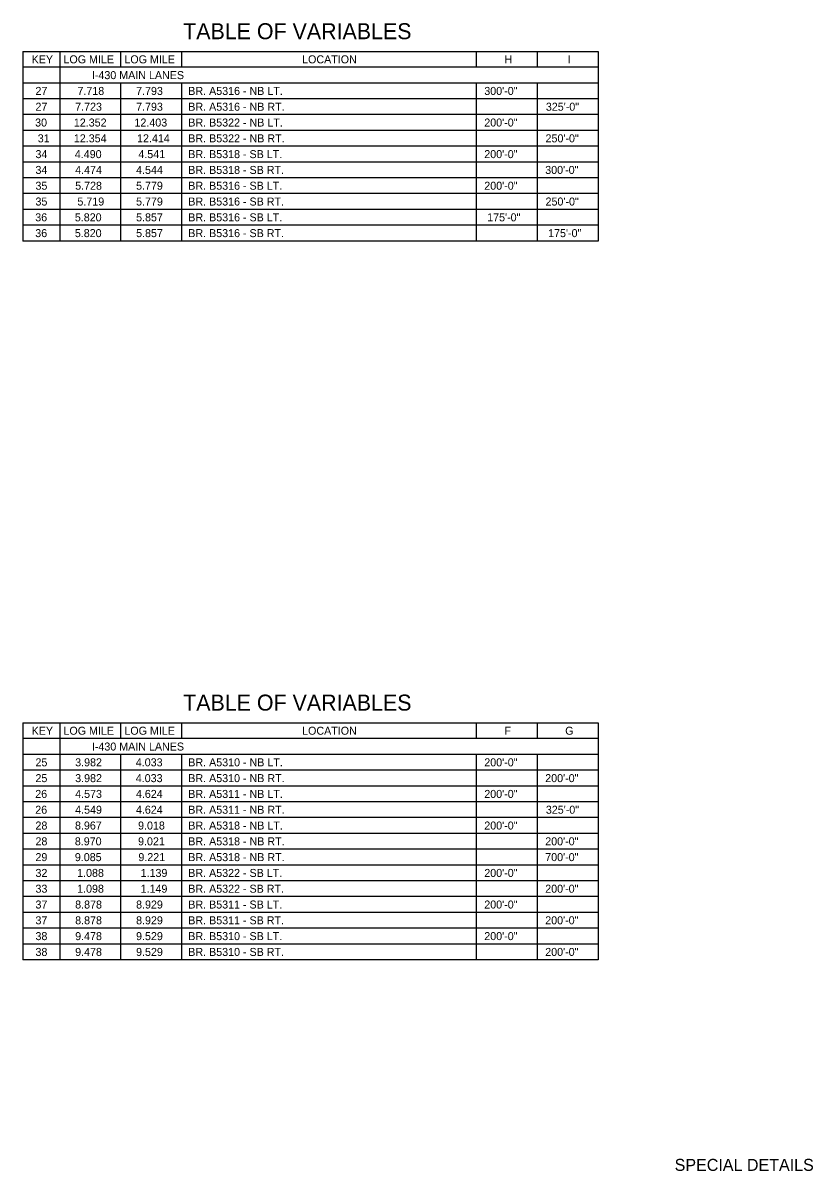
# Model space of a CAD drawing. Extents: x 1373853 to 1374003, y 380191 to 380927.
# Drawn here: x 1373943.9 to 1374003.2, y 380190.6 to 380276.6 of the extents above; entities that cross this region are included whole.
import ezdxf

# ---------------------------------------------------------------- set-up
doc = ezdxf.new("R2010")
doc.units = 0
for name, color, linetype in [('2', 7, 'Continuous'), ('8', 7, 'Continuous'), ('G-ANNO-TEXT', 7, 'Continuous'), ('Plan Notes', 7, 'Continuous')]:
    doc.layers.add(name, color=color, linetype=linetype)

msp = doc.modelspace()

# ---------------------------------------------------------------- linework, layer by layer
at = {"layer": 'Plan Notes'}
for p, q in [((1373943.931, 380274.494), (1373987.072, 380274.494)), ((1373943.931, 380274.494), (1373943.931, 380260.28)), ((1373946.688, 380274.494), (1373946.688, 380260.28)), ((1373951.258, 380274.494), (1373951.258, 380273.31)), ((1373955.827, 380274.494), (1373955.827, 380273.31)), ((1373977.932, 380274.494), (1373977.932, 380273.31)), ((1373982.502, 380274.494), (1373982.502, 380273.31)), ((1373987.072, 380274.494), (1373987.072, 380260.28)), ((1373951.258, 380272.125), (1373951.258, 380260.28)), ((1373955.827, 380272.125), (1373955.827, 380260.28)), ((1373977.932, 380272.125), (1373977.932, 380260.28)), ((1373982.502, 380272.125), (1373982.502, 380260.28)), ((1373943.931, 380224.155), (1373987.072, 380224.155)), ((1373943.931, 380224.155), (1373943.931, 380206.387)), ((1373946.688, 380224.155), (1373946.688, 380206.387)), ((1373951.258, 380224.155), (1373951.258, 380222.971)), ((1373955.827, 380224.155), (1373955.827, 380222.971)), ((1373977.932, 380224.155), (1373977.932, 380222.971)), ((1373982.502, 380224.155), (1373982.502, 380222.971)), ((1373987.072, 380224.155), (1373987.072, 380206.387)), ((1373951.258, 380221.786), (1373951.258, 380206.387)), ((1373955.827, 380221.786), (1373955.827, 380206.387)), ((1373977.932, 380221.786), (1373977.932, 380206.387)), ((1373982.502, 380221.786), (1373982.502, 380206.387))]:
    msp.add_line(p, q, dxfattribs=at)
for points in [[(1373987.072, 380273.31), (1373943.931, 380273.31)], [(1373987.072, 380272.125), (1373943.931, 380272.125)], [(1373987.072, 380270.941), (1373943.931, 380270.941)], [(1373987.072, 380269.756), (1373943.931, 380269.756)], [(1373987.072, 380268.572), (1373943.931, 380268.572)], [(1373987.072, 380267.387), (1373943.931, 380267.387)], [(1373987.072, 380267.387), (1373943.931, 380267.387)], [(1373987.072, 380266.203), (1373943.931, 380266.203)], [(1373987.072, 380265.018), (1373943.931, 380265.018)], [(1373987.072, 380263.834), (1373943.931, 380263.834)], [(1373987.072, 380262.649), (1373943.931, 380262.649)], [(1373987.072, 380262.649), (1373943.931, 380262.649)], [(1373987.072, 380261.465), (1373943.931, 380261.465)], [(1373987.072, 380260.28), (1373943.931, 380260.28)], [(1373987.072, 380222.971), (1373943.931, 380222.971)], [(1373987.072, 380221.786), (1373943.931, 380221.786)], [(1373987.072, 380220.602), (1373943.931, 380220.602)], [(1373987.072, 380219.417), (1373943.931, 380219.417)], [(1373987.072, 380218.233), (1373943.931, 380218.233)], [(1373987.072, 380217.048), (1373943.931, 380217.048)], [(1373987.072, 380217.048), (1373943.931, 380217.048)], [(1373987.072, 380215.864), (1373943.931, 380215.864)], [(1373987.072, 380214.679), (1373943.931, 380214.679)], [(1373987.072, 380213.494), (1373943.931, 380213.494)], [(1373987.072, 380212.31), (1373943.931, 380212.31)], [(1373987.072, 380212.31), (1373943.931, 380212.31)], [(1373987.072, 380211.125), (1373943.931, 380211.125)], [(1373987.072, 380209.941), (1373943.931, 380209.941)], [(1373987.072, 380208.756), (1373943.931, 380208.756)], [(1373987.072, 380207.572), (1373943.931, 380207.572)], [(1373987.072, 380206.387), (1373943.931, 380206.387)]]:
    msp.add_lwpolyline(points, dxfattribs=at)

# ---------------------------------------------------------------- texts
at = {"layer": '2'}
for s, p in [('KEY', (1373944.582, 380273.602)), ('LOG MILE', (1373946.969, 380273.602)), ('LOG MILE', (1373951.539, 380273.602)), ('LOCATION', (1373964.869, 380273.602)), ('H', (1373980.047, 380273.602)), ('I', (1373984.787, 380273.602)), ('I-430 MAIN LANES', (1373949.101, 380272.418)), ('27', (1373944.87, 380271.233)), ('7.718', (1373948.018, 380271.233)), ('7.793', (1373952.418, 380271.233)), ('BR. A5316 - NB LT.', (1373956.331, 380271.233)), ('300\'-0"', (1373978.532, 380271.233)), ('27', (1373944.87, 380270.049)), ('7.723', (1373947.848, 380270.049)), ('7.793', (1373952.418, 380270.049)), ('BR. A5316 - NB RT.', (1373956.331, 380270.049)), ('325\'-0"', (1373983.15, 380270.049)), ('30', (1373944.844, 380268.864)), ('12.352', (1373947.749, 380268.864)), ('12.403', (1373952.295, 380268.864)), ('BR. B5322 - NB LT.', (1373956.331, 380268.864)), ('200\'-0"', (1373978.532, 380268.864)), ('31', (1373945.04, 380267.68)), ('12.354', (1373947.749, 380267.68)), ('12.414', (1373952.489, 380267.68)), ('BR. B5322 - NB RT.', (1373956.331, 380267.68)), ('250\'-0"', (1373983.126, 380267.68)), ('34', (1373944.87, 380266.495)), ('4.490', (1373947.822, 380266.495)), ('4.541', (1373952.588, 380266.495)), ('BR. B5318 - SB LT.', (1373956.331, 380266.495)), ('200\'-0"', (1373978.532, 380266.495)), ('34', (1373944.87, 380265.31)), ('4.474', (1373947.848, 380265.31)), ('4.544', (1373952.418, 380265.31)), ('BR. B5318 - SB RT.', (1373956.331, 380265.31)), ('300\'-0"', (1373983.102, 380265.31)), ('35', (1373944.87, 380264.126)), ('5.728', (1373947.848, 380264.126)), ('5.779', (1373952.416, 380264.126)), ('BR. B5316 - SB LT.', (1373956.331, 380264.126)), ('200\'-0"', (1373978.532, 380264.126)), ('35', (1373944.87, 380262.941)), ('5.719', (1373948.016, 380262.941)), ('5.779', (1373952.416, 380262.941)), ('BR. B5316 - SB RT.', (1373956.331, 380262.941)), ('250\'-0"', (1373983.126, 380262.941)), ('36', (1373944.853, 380261.757)), ('5.820', (1373947.822, 380261.757)), ('5.857', (1373952.418, 380261.757)), ('BR. B5316 - SB LT.', (1373956.331, 380261.757)), ('175\'-0"', (1373978.75, 380261.757)), ('36', (1373944.853, 380260.572)), ('5.820', (1373947.822, 380260.572)), ('5.857', (1373952.418, 380260.572)), ('BR. B5316 - SB RT.', (1373956.331, 380260.572)), ('175\'-0"', (1373983.32, 380260.572)), ('KEY', (1373944.582, 380223.263)), ('LOG MILE', (1373946.969, 380223.263)), ('LOG MILE', (1373951.539, 380223.263)), ('LOCATION', (1373964.869, 380223.263)), ('F', (1373980.044, 380223.263)), ('G', (1373984.6, 380223.263)), ('I-430 MAIN LANES', (1373949.101, 380222.078)), ('25', (1373944.87, 380220.894)), ('3.982', (1373947.848, 380220.894)), ('4.033', (1373952.394, 380220.894)), ('BR. A5310 - NB LT.', (1373956.331, 380220.894)), ('200\'-0"', (1373978.532, 380220.894)), ('25', (1373944.87, 380219.709)), ('3.982', (1373947.848, 380219.709)), ('4.033', (1373952.394, 380219.709)), ('BR. A5310 - NB RT.', (1373956.331, 380219.709)), ('200\'-0"', (1373983.102, 380219.709)), ('26', (1373944.853, 380218.525)), ('4.573', (1373947.848, 380218.525)), ('4.624', (1373952.404, 380218.525)), ('BR. A5311 - NB LT.', (1373956.331, 380218.525)), ('200\'-0"', (1373978.532, 380218.525)), ('26', (1373944.853, 380217.34)), ('4.549', (1373947.846, 380217.34)), ('4.624', (1373952.404, 380217.34)), ('BR. A5311 - NB RT.', (1373956.331, 380217.34)), ('325\'-0"', (1373983.15, 380217.34)), ('28', (1373944.87, 380216.156)), ('8.967', (1373947.834, 380216.156)), ('9.018', (1373952.565, 380216.156)), ('BR. A5318 - NB LT.', (1373956.331, 380216.156)), ('200\'-0"', (1373978.532, 380216.156)), ('28', (1373944.87, 380214.971)), ('8.970', (1373947.822, 380214.971)), ('9.021', (1373952.565, 380214.971)), ('BR. A5318 - NB RT.', (1373956.331, 380214.971)), ('200\'-0"', (1373983.102, 380214.971)), ('29', (1373944.868, 380213.787)), ('9.085', (1373947.824, 380213.787)), ('9.221', (1373952.588, 380213.787)), ('BR. A5318 - NB RT.', (1373956.331, 380213.787)), ('700\'-0"', (1373983.102, 380213.787)), ('32', (1373944.87, 380212.602)), ('1.088', (1373947.995, 380212.602)), ('1.139', (1373952.756, 380212.602)), ('BR. A5322 - SB LT.', (1373956.331, 380212.602)), ('200\'-0"', (1373978.532, 380212.602)), ('33', (1373944.87, 380211.418)), ('1.098', (1373947.995, 380211.418)), ('1.149', (1373952.756, 380211.418)), ('BR. A5322 - SB RT.', (1373956.331, 380211.418)), ('200\'-0"', (1373983.102, 380211.418)), ('37', (1373944.87, 380210.233)), ('8.878', (1373947.848, 380210.233)), ('8.929', (1373952.416, 380210.233)), ('BR. B5311 - SB LT.', (1373956.331, 380210.233)), ('200\'-0"', (1373978.532, 380210.233)), ('37', (1373944.87, 380209.049)), ('8.878', (1373947.848, 380209.049)), ('8.929', (1373952.416, 380209.049)), ('BR. B5311 - SB RT.', (1373956.331, 380209.049)), ('200\'-0"', (1373983.102, 380209.049)), ('38', (1373944.87, 380207.864)), ('9.478', (1373947.848, 380207.864)), ('9.529', (1373952.416, 380207.864)), ('BR. B5310 - SB LT.', (1373956.331, 380207.864)), ('200\'-0"', (1373978.532, 380207.864)), ('38', (1373944.87, 380206.679)), ('9.478', (1373947.848, 380206.679)), ('9.529', (1373952.416, 380206.679)), ('BR. B5310 - SB RT.', (1373956.331, 380206.679)), ('200\'-0"', (1373983.102, 380206.679))]:
    msp.add_text(s, height=0.6, rotation=0.00003, dxfattribs=at).set_placement(p)
at = {"layer": '8'}
for p in [(1373955.949, 380275.411), (1373955.949, 380225.072)]:
    msp.add_text('TABLE OF VARIABLES', height=1.2, rotation=0.00003, dxfattribs=at).set_placement(p)
at = {"layer": 'G-ANNO-TEXT'}
msp.add_text('SPECIAL DETAILS', height=0.9, dxfattribs=at).set_placement((1373992.81, 380190.563))

doc.saveas('drawing.dxf')
